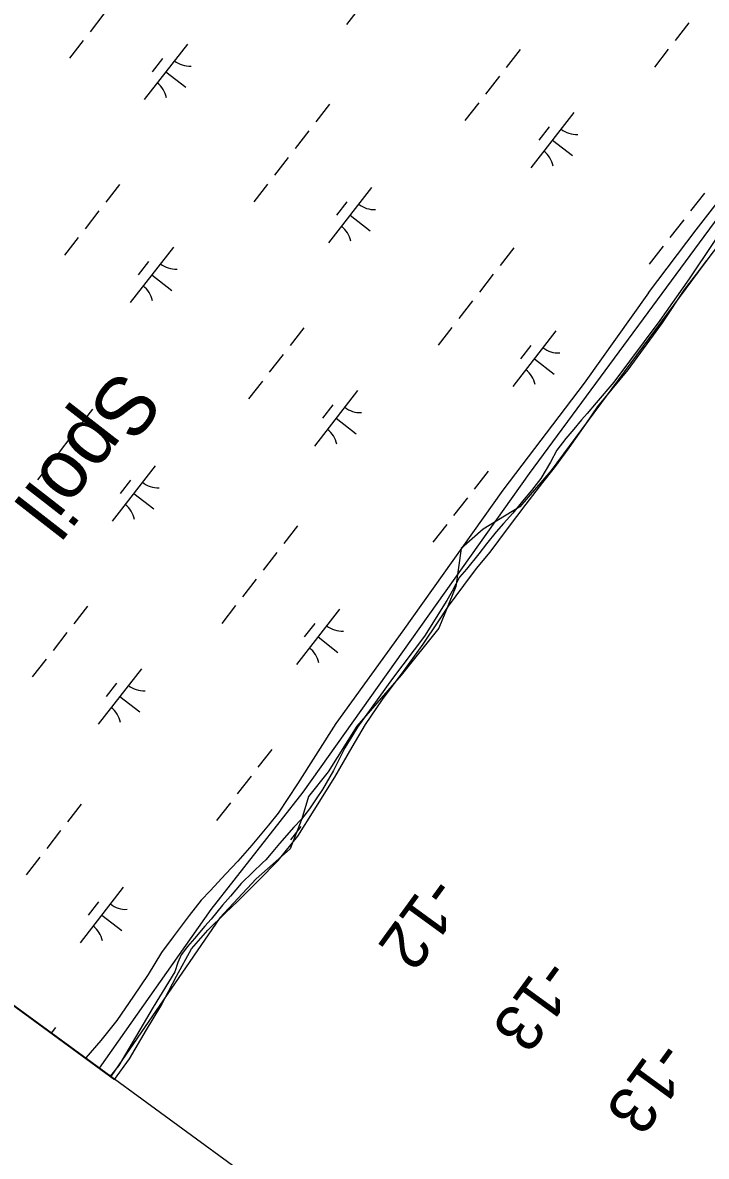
# Model space of a CAD drawing. Extents: x 3888273 to 3909528, y 158682 to 181032.
# Drawn here: x 3894934 to 3895421, y 162927 to 163734 of the extents above; entities that cross this region are included whole.
import ezdxf

# ---------------------------------------------------------------- set-up
doc = ezdxf.new("R2010")
doc.units = 0
for name, color, linetype in [('V-CHAN-SPOL', 7, 'Continuous'), ('V-GRID-FRAM', 7, 'Continuous'), ('V-RIVR-EDGE', 7, 'Continuous'), ('V-RIVR-JETY', 7, 'Continuous'), ('V-RIVR-RANG', 7, 'Continuous'), ('V-RRAP-FSHR', 7, 'Continuous'), ('V-WETL-SWMP', 7, 'Continuous')]:
    doc.layers.add(name, color=color, linetype=linetype)

msp = doc.modelspace()

# ---------------------------------------------------------------- linework, layer by layer
at = {"layer": 'V-GRID-FRAM'}
msp.add_lwpolyline([(3907415.04, 172254.23), (3898317.3, 160561.45), (3891517.26, 165521.58), (3900698.93, 177323.83), (3907415.04, 172254.23)], dxfattribs=at)
at = {"layer": 'V-RIVR-EDGE'}
msp.add_lwpolyline([(3895720.24, 163959.74), (3895419.18, 163562.04), (3895310.46, 163415.22), (3895288.16, 163389.21), (3895262.14, 163373.41), (3895246.35, 163359.47), (3895242.63, 163332.53), (3895230.55, 163302.79), (3895203.6, 163269.34), (3895172.01, 163233.1), (3895151.57, 163200.58), (3895137.63, 163182.92), (3895132.98, 163167.13), (3895124.62, 163145.75), (3895100.46, 163124.38), (3895074.44, 163096.51), (3894996.77, 162983.53)], dxfattribs=at)
at = {"layer": 'V-RIVR-JETY'}
for points in [[(3895379.8, 163541.66), (3895413.81, 163586.51), (3895452.17, 163635.64)], [(3895444.11, 163603.94), (3895408.87, 163551.66), (3895387.91, 163521.86)], [(3895379.8, 163541.66), (3895334.02, 163477.29), (3895276.07, 163401.2), (3895204.87, 163300.96), (3895157.06, 163234.91), (3895129.92, 163191.98), (3895116.01, 163171.19), (3895109.23, 163162.47), (3895097.38, 163148.4), (3895087.22, 163137.01), (3895078.76, 163127.97), (3895067.59, 163115.92), (3895061.16, 163109.22), (3895052.69, 163098.16), (3895041.17, 163083.07), (3895033.03, 163072.01), (3895023.52, 163056.24), (3895013.01, 163040.82), (3895001.14, 163023.38), (3894989.62, 163009.31), (3894979.12, 162996.91), (3894978.87, 162996.59)], [(3895387.91, 163521.86), (3895355.28, 163477.89), (3895342.65, 163463.38), (3895336.13, 163455.72), (3895332.06, 163451.29), (3895326.76, 163444.44), (3895321.06, 163437.99), (3895314.53, 163429.52), (3895310.04, 163421.04), (3895303.09, 163409.33), (3895296.57, 163400.86), (3895290.05, 163393.21), (3895283.12, 163384.74), (3895276.6, 163377.48), (3895271.31, 163371.44), (3895264.38, 163362.97), (3895259.07, 163355.71), (3895250.11, 163344.83), (3895245.22, 163339.18), (3895239.9, 163329.09), (3895236.22, 163322.63), (3895220.29, 163297.21), (3895197.46, 163266.96), (3895172.58, 163232.27), (3895168.49, 163225.81), (3895163.59, 163217.73), (3895159.91, 163210.47), (3895155.41, 163201.58), (3895147.64, 163187.86), (3895143.15, 163181.4), (3895138.25, 163174.14), (3895132.55, 163166.88), (3895127.25, 163161.24), (3895117.07, 163149.55), (3895110.96, 163142.29), (3895107.29, 163137.86), (3895104.85, 163135.85), (3895097.93, 163129), (3895089.79, 163120.95), (3895082.04, 163112.08), (3895076.34, 163105.63), (3895068.19, 163095.55), (3895063.71, 163090.71), (3895056.38, 163081.85), (3895051.49, 163076.2), (3895047, 163070.15), (3895044.54, 163064.9), (3895042.48, 163058.03), (3895026.96, 163033.01), (3895002.45, 162991.43), (3894996.35, 162983.84)]]:
    msp.add_lwpolyline(points, dxfattribs=at)
at = {"layer": 'V-RRAP-FSHR'}
msp.add_lwpolyline([(3897040.66, 166435.14), (3896938.06, 166249.62), (3896609.52, 165663.62), (3896599.21, 165639.82), (3896417.98, 165214.47), (3896375.9, 165110.36), (3896269.9, 164887.71), (3896216.93, 164792.83), (3896076.26, 164523.63), (3895950.84, 164293.14), (3895897.31, 164215.5), (3895842.22, 164133.18), (3895759.52, 164026.76), (3895629.16, 163860.22), (3895446.62, 163618.63), (3895294.79, 163412.93), (3895133.58, 163186.13), (3895068.02, 163102.49), (3894988.6, 162989.5)], dxfattribs=at)
at = {"layer": 'V-WETL-SWMP'}
for p, q in [((3893763.22, 163883.31), (3894999.45, 162981.57)), ((3895195.5, 163772.22), (3895164.79, 163732.75)), ((3894991.94, 163740.16), (3894982.12, 163727.53)), ((3895408.61, 163733.93), (3895398.79, 163721.31)), ((3894977.21, 163721.22), (3894967.38, 163708.59)), ((3895051.35, 163718.75), (3895020.65, 163679.28)), ((3895288.41, 163714.75), (3895278.59, 163702.12)), ((3895393.87, 163714.99), (3895384.05, 163702.37)), ((3895033.59, 163708.49), (3895026.22, 163699.02)), ((3895036, 163699.01), (3895050.2, 163687.96)), ((3895273.67, 163695.81), (3895263.85, 163683.18)), ((3895152.7, 163675.9), (3895142.88, 163663.27)), ((3895258.94, 163676.87), (3895249.11, 163664.24)), ((3895326.78, 163670.07), (3895296.07, 163630.61)), ((3895309.02, 163659.81), (3895301.65, 163650.34)), ((3895137.96, 163656.96), (3895128.14, 163644.33)), ((3895311.42, 163650.34), (3895325.63, 163639.29)), ((3895123.23, 163638.02), (3895113.4, 163625.39)), ((3895003.02, 163618.83), (3894993.2, 163606.2)), ((3895108.49, 163619.07), (3895098.66, 163606.45)), ((3895182.63, 163616.6), (3895151.93, 163577.14)), ((3895419.69, 163612.61), (3895409.87, 163599.98)), ((3895164.87, 163606.34), (3895157.5, 163596.87)), ((3894988.29, 163599.89), (3894978.46, 163587.26)), ((3895167.28, 163596.87), (3895181.48, 163585.82)), ((3895404.95, 163593.66), (3895395.13, 163581.04)), ((3894973.55, 163580.95), (3894963.72, 163568.32)), ((3895041.39, 163574.15), (3895010.69, 163534.69)), ((3895283.98, 163573.75), (3895274.16, 163561.13)), ((3895390.22, 163574.72), (3895380.39, 163562.09)), ((3895023.63, 163563.89), (3895016.26, 163554.42)), ((3895414.1, 163554.84), (3895421.4, 163564.53)), ((3895026.04, 163554.42), (3895040.24, 163543.37)), ((3895269.24, 163554.81), (3895259.42, 163542.19)), ((3895405.79, 163544.17), (3895414.1, 163554.84)), ((3895389.9, 163520.32), (3895405.79, 163544.17)), ((3895254.51, 163535.87), (3895244.68, 163523.24)), ((3895365.42, 163486.83), (3895389.9, 163520.32)), ((3895134.31, 163516.69), (3895124.48, 163504.06)), ((3895239.77, 163516.93), (3895229.94, 163504.3)), ((3895313.91, 163514.46), (3895283.21, 163474.99)), ((3895296.15, 163504.2), (3895288.79, 163494.73)), ((3895119.57, 163497.75), (3895109.74, 163485.12)), ((3895298.56, 163494.73), (3895312.77, 163483.67)), ((3895354.01, 163473.12), (3895365.42, 163486.83)), ((3894998.6, 163477.84), (3894988.77, 163465.21)), ((3895104.83, 163478.8), (3895095, 163466.18)), ((3895172.67, 163472.01), (3895141.97, 163432.55)), ((3895343.82, 163460.61), (3895354.01, 163473.12)), ((3894983.86, 163458.89), (3894974.03, 163446.27)), ((3895154.91, 163461.75), (3895147.54, 163452.28)), ((3895335.25, 163448.11), (3895343.82, 163460.61)), ((3895157.32, 163452.28), (3895171.52, 163441.22)), ((3895323.41, 163431.16), (3895335.25, 163448.11)), ((3894969.12, 163439.95), (3894959.29, 163427.32)), ((3895312.8, 163417.04), (3895323.41, 163431.16)), ((3894954.38, 163421.01), (3894944.56, 163408.38)), ((3895028.52, 163418.54), (3894997.82, 163379.08)), ((3895304.65, 163406.55), (3895312.8, 163417.04)), ((3895010.77, 163408.28), (3895003.4, 163398.81)), ((3895265.59, 163414.54), (3895255.76, 163401.91)), ((3895292.82, 163391.22), (3895304.65, 163406.55)), ((3895013.17, 163398.81), (3895027.38, 163387.75)), ((3895250.85, 163395.6), (3895241.02, 163382.97)), ((3895279.36, 163373.47), (3895292.82, 163391.22)), ((3895129.88, 163375.69), (3895120.05, 163363.06)), ((3895236.11, 163376.66), (3895226.28, 163364.03)), ((3895267.12, 163356.93), (3895279.36, 163373.47)), ((3895115.14, 163356.75), (3895105.31, 163344.12)), ((3895257.34, 163345.23), (3895267.12, 163356.93)), ((3895248.36, 163333.13), (3895257.34, 163345.23)), ((3895100.4, 163337.81), (3895090.57, 163325.18)), ((3895237.35, 163318.61), (3895248.36, 163333.13)), ((3894980.2, 163318.62), (3894970.37, 163306)), ((3895085.66, 163318.87), (3895075.84, 163306.24)), ((3895230, 163307.3), (3895237.35, 163318.61)), ((3895159.8, 163316.39), (3895129.1, 163276.93)), ((3895142.05, 163306.13), (3895134.68, 163296.66)), ((3895219.39, 163291.57), (3895230, 163307.3)), ((3894965.46, 163299.68), (3894955.64, 163287.05)), ((3895144.45, 163296.66), (3895158.66, 163285.61)), ((3895203.88, 163270.18), (3895219.39, 163291.57)), ((3894950.72, 163280.74), (3894940.9, 163268.11)), ((3895018.56, 163273.94), (3894987.86, 163234.48)), ((3895198.58, 163263.32), (3895203.88, 163270.18)), ((3895000.81, 163263.69), (3894993.44, 163254.22)), ((3895190.42, 163252.02), (3895198.58, 163263.32)), ((3895003.21, 163254.21), (3895017.42, 163243.16)), ((3895178.17, 163234.27), (3895190.42, 163252.02)), ((3895168.77, 163218.12), (3895178.17, 163234.27)), ((3895111.48, 163216.48), (3895101.65, 163203.85)), ((3895156.51, 163196.71), (3895168.77, 163218.12)), ((3895096.74, 163197.54), (3895086.92, 163184.91)), ((3895141.8, 163173.3), (3895156.51, 163196.71)), ((3894975.77, 163177.63), (3894965.94, 163165)), ((3895082, 163178.59), (3895072.18, 163165.97)), ((3895129.96, 163154.73), (3895141.8, 163173.3)), ((3894961.03, 163158.69), (3894951.21, 163146.06)), ((3895132.09, 163161.54), (3895124.72, 163152.07)), ((3895116.09, 163137.39), (3895129.96, 163154.73)), ((3894946.29, 163139.74), (3894936.47, 163127.12)), ((3895101.84, 163122.88), (3895116.09, 163137.39)), ((3895005.7, 163118.33), (3894974.99, 163078.87)), ((3895087.59, 163108.78), (3895101.84, 163122.88)), ((3895078.23, 163099.92), (3895087.59, 163108.78)), ((3894987.94, 163108.07), (3894980.57, 163098.6)), ((3894990.35, 163098.6), (3895004.55, 163087.54)), ((3895066.01, 163087.83), (3895078.23, 163099.92)), ((3895054.2, 163074.53), (3895066.01, 163087.83)), ((3895043.56, 163055.15), (3895054.2, 163074.53)), ((3895032.51, 163033.74), (3895043.56, 163055.15)), ((3895022.3, 163016.78), (3895032.51, 163033.74)), ((3894957.37, 163018.41), (3894954.32, 163014.49)), ((3895010.04, 162996.19), (3895022.3, 163016.78)), ((3894999.45, 162981.57), (3895010.04, 162996.19))]:
    msp.add_line(p, q, dxfattribs=at)
for centre, start, end in [((3895053.15, 163720.67), 231.34298, 272.88664), ((3895019.22, 163677.07), 11.34298, 52.88663), ((3895328.57, 163671.99), 231.34298, 272.88664), ((3895294.65, 163628.39), 11.34298, 52.88663), ((3895184.43, 163618.52), 231.34298, 272.88664), ((3895150.5, 163574.92), 11.34298, 52.88663), ((3895043.19, 163576.08), 231.34298, 272.88664), ((3895009.26, 163532.48), 11.34298, 52.88663), ((3895315.71, 163516.38), 231.34298, 272.88664), ((3895281.78, 163472.78), 11.34298, 52.88663), ((3895174.47, 163473.93), 231.34298, 272.88664), ((3895140.54, 163430.33), 11.34298, 52.88663), ((3895030.32, 163420.46), 231.34298, 272.88664), ((3894996.4, 163376.86), 11.34298, 52.88663), ((3895161.6, 163318.32), 231.34298, 272.88664), ((3895127.68, 163274.72), 11.34298, 52.88663), ((3895020.36, 163275.87), 231.34298, 272.88664), ((3894986.44, 163232.27), 11.34298, 52.88663), ((3895007.5, 163120.25), 231.34298, 272.88664), ((3894973.57, 163076.65), 11.34298, 52.88663)]:
    msp.add_arc(centre, 17.62, start, end, dxfattribs=at)

# ---------------------------------------------------------------- texts
at = {"layer": 'V-CHAN-SPOL'}
msp.add_text('Spoil', height=42, rotation=232.11852, dxfattribs=at).set_placement((3895002.59, 163488.57))
at = {"layer": 'V-RIVR-RANG'}
for s, p in [('-12', (3895224.17, 163128.63)), ('-13', (3895305.35, 163070.24)), ('-13', (3895386.38, 163011.63))]:
    msp.add_text(s, height=33.5, rotation=233.97833, dxfattribs=at).set_placement(p)

doc.saveas('drawing.dxf')
